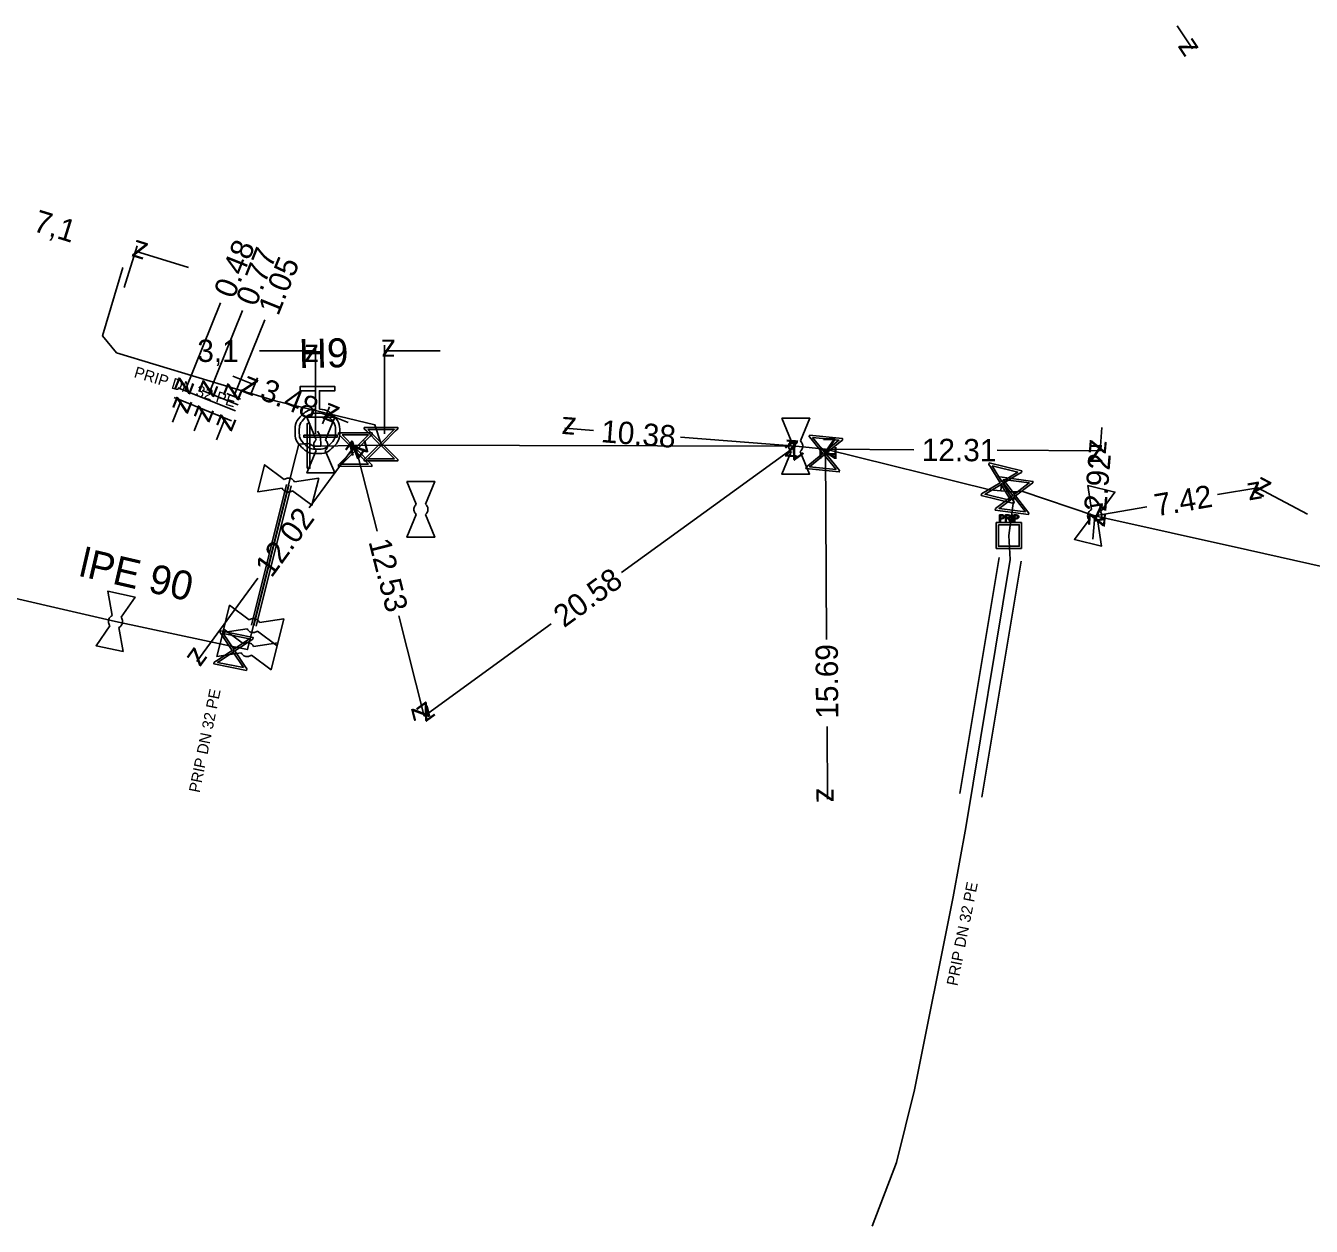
# Model space of a CAD drawing. Extents: x -638315 to -636370, y -1116147 to -1115110.
# Drawn here: x -637168.7 to -637111.1, y -1116084.9 to -1116031.1 of the extents above; entities that cross this region are included whole.
import ezdxf

# ---------------------------------------------------------------- set-up
doc = ezdxf.new("R2010")
doc.units = 0
for name, color, linetype in [('Default', 7, 'Continuous'), ('VP Chránička', 7, 'Continuous'), ('VP Chránička - okraje', 7, 'Continuous'), ('VP Hydrant', 7, 'Continuous'), ('VP Hydrant - popis', 7, 'Continuous'), ('VP Kótování', 7, 'Continuous'), ('VP Lomový bod', 7, 'Continuous'), ('VP Popis přípojky', 7, 'Continuous'), ('VP Přípojka', 7, 'Continuous'), ('VP Řad', 7, 'Continuous'), ('VP Řad - popis', 7, 'Continuous'), ('VP Šachta', 7, 'Continuous'), ('VP Šoupě', 7, 'Continuous')]:
    doc.layers.add(name, color=color, linetype=linetype)

msp = doc.modelspace()

# ---------------------------------------------------------------- linework, layer by layer
at = {"layer": 'Default'}
for points in [[(-637155.578, -1116048.304), (-637155.219, -1116048.333), (-637154.961, -1116048.593), (-637154.67, -1116048.886), (-637154.67, -1116049.302), (-637154.67, -1116049.716), (-637154.963, -1116050.008), (-637155.256, -1116050.3), (-637155.672, -1116050.3), (-637156.084, -1116050.3), (-637156.377, -1116050.008), (-637156.67, -1116049.716), (-637156.67, -1116049.302), (-637156.67, -1116048.886), (-637156.379, -1116048.593), (-637156.121, -1116048.331), (-637155.762, -1116048.304)], [(-637155.672, -1116048.486), (-637156.01, -1116048.486), (-637156.247, -1116048.723), (-637156.484, -1116048.96), (-637156.484, -1116049.298), (-637156.484, -1116049.636), (-637156.247, -1116049.873), (-637156.01, -1116050.111), (-637155.672, -1116050.111), (-637155.336, -1116050.111), (-637155.098, -1116049.873), (-637154.859, -1116049.636), (-637154.859, -1116049.298), (-637154.859, -1116048.96), (-637155.097, -1116048.723), (-637155.334, -1116048.486), (-637155.672, -1116048.486)], [(-637155.724, -1116050.157), (-637155.764, -1116050.123), (-637155.791, -1116050.075), (-637155.833, -1116050.002), (-637155.833, -1116049.92), (-637155.833, -1116049.838), (-637155.79, -1116049.763), (-637155.764, -1116049.716), (-637155.724, -1116049.682)], [(-637155.315, -1116049.682), (-637155.276, -1116049.716), (-637155.249, -1116049.763), (-637155.208, -1116049.838), (-637155.208, -1116049.92), (-637155.208, -1116050.002), (-637155.249, -1116050.075), (-637155.276, -1116050.123), (-637155.316, -1116050.157)], [(-637134.434, -1116050.206), (-637134.475, -1116050.172), (-637134.501, -1116050.124), (-637134.543, -1116050.051), (-637134.543, -1116049.969), (-637134.542, -1116049.887), (-637134.499, -1116049.812), (-637134.474, -1116049.766), (-637134.433, -1116049.731)], [(-637134.024, -1116049.732), (-637133.985, -1116049.767), (-637133.959, -1116049.813), (-637133.917, -1116049.889), (-637133.918, -1116049.971), (-637133.918, -1116050.052), (-637133.959, -1116050.126), (-637133.986, -1116050.173), (-637134.027, -1116050.207)], [(-637157.158, -1116051.458), (-637157.115, -1116051.428), (-637157.062, -1116051.413), (-637156.981, -1116051.39), (-637156.902, -1116051.41), (-637156.822, -1116051.43), (-637156.759, -1116051.489), (-637156.72, -1116051.526), (-637156.697, -1116051.573)], [(-637156.795, -1116051.97), (-637156.838, -1116051.999), (-637156.889, -1116052.014), (-637156.973, -1116052.036), (-637157.052, -1116052.017), (-637157.132, -1116051.997), (-637157.193, -1116051.939), (-637157.232, -1116051.901), (-637157.256, -1116051.854)], [(-637151.237, -1116053.039), (-637151.278, -1116053.005), (-637151.305, -1116052.958), (-637151.346, -1116052.884), (-637151.346, -1116052.803), (-637151.346, -1116052.721), (-637151.303, -1116052.645), (-637151.278, -1116052.599), (-637151.237, -1116052.564)], [(-637150.829, -1116052.564), (-637150.789, -1116052.599), (-637150.763, -1116052.645), (-637150.721, -1116052.721), (-637150.721, -1116052.803), (-637150.721, -1116052.884), (-637150.763, -1116052.958), (-637150.789, -1116053.005), (-637150.83, -1116053.039)], [(-637124.984, -1116053.054), (-637124.955, -1116053.054), (-637124.94, -1116053.057), (-637124.919, -1116053.061), (-637124.905, -1116053.071), (-637124.89, -1116053.08), (-637124.882, -1116053.098), (-637124.873, -1116053.116), (-637124.873, -1116053.137), (-637124.873, -1116053.174), (-637124.896, -1116053.199), (-637124.919, -1116053.224), (-637124.98, -1116053.224)], [(-637124.98, -1116053.191), (-637124.943, -1116053.191), (-637124.928, -1116053.177), (-637124.912, -1116053.163), (-637124.912, -1116053.138), (-637124.912, -1116053.12), (-637124.921, -1116053.108), (-637124.93, -1116053.095), (-637124.945, -1116053.091), (-637124.954, -1116053.088), (-637124.981, -1116053.088)], [(-637124.716, -1116053.181), (-637124.69, -1116053.181), (-637124.675, -1116053.176), (-637124.66, -1116053.17), (-637124.653, -1116053.158), (-637124.646, -1116053.147), (-637124.646, -1116053.132), (-637124.646, -1116053.113), (-637124.66, -1116053.099), (-637124.675, -1116053.086), (-637124.707, -1116053.086)], [(-637124.708, -1116053.054), (-637124.67, -1116053.054), (-637124.65, -1116053.062), (-637124.63, -1116053.07), (-637124.618, -1116053.089), (-637124.607, -1116053.109), (-637124.607, -1116053.132), (-637124.607, -1116053.163), (-637124.626, -1116053.184), (-637124.646, -1116053.204), (-637124.687, -1116053.21), (-637124.672, -1116053.218), (-637124.664, -1116053.225), (-637124.648, -1116053.24), (-637124.633, -1116053.263)], [(-637124.342, -1116053.055), (-637124.314, -1116053.055), (-637124.298, -1116053.058), (-637124.278, -1116053.062), (-637124.263, -1116053.072), (-637124.248, -1116053.081), (-637124.24, -1116053.099), (-637124.232, -1116053.116), (-637124.232, -1116053.138), (-637124.232, -1116053.175), (-637124.255, -1116053.2), (-637124.278, -1116053.225), (-637124.338, -1116053.225)], [(-637124.338, -1116053.192), (-637124.301, -1116053.192), (-637124.286, -1116053.178), (-637124.271, -1116053.164), (-637124.271, -1116053.139), (-637124.271, -1116053.121), (-637124.28, -1116053.109), (-637124.288, -1116053.096), (-637124.303, -1116053.092), (-637124.313, -1116053.089), (-637124.339, -1116053.089)], [(-637121.084, -1116053.271), (-637121.115, -1116053.228), (-637121.13, -1116053.175), (-637121.153, -1116053.094), (-637121.133, -1116053.015), (-637121.113, -1116052.935), (-637121.054, -1116052.872), (-637121.018, -1116052.833), (-637120.97, -1116052.81)], [(-637120.573, -1116052.908), (-637120.544, -1116052.95), (-637120.529, -1116053.002), (-637120.507, -1116053.085), (-637120.526, -1116053.165), (-637120.546, -1116053.244), (-637120.604, -1116053.305), (-637120.641, -1116053.345), (-637120.688, -1116053.368)], [(-637124.668, -1116053.282), (-637124.685, -1116053.255), (-637124.696, -1116053.241), (-637124.706, -1116053.228), (-637124.715, -1116053.222), (-637124.724, -1116053.217), (-637124.733, -1116053.215), (-637124.739, -1116053.213), (-637124.753, -1116053.213)], [(-637164.97, -1116058.02), (-637165.001, -1116057.978), (-637165.018, -1116057.927), (-637165.043, -1116057.844), (-637165.026, -1116057.765), (-637165.008, -1116057.685), (-637164.952, -1116057.622), (-637164.916, -1116057.581), (-637164.87, -1116057.556)], [(-637164.471, -1116057.641), (-637164.439, -1116057.683), (-637164.423, -1116057.735), (-637164.397, -1116057.816), (-637164.414, -1116057.895), (-637164.432, -1116057.975), (-637164.489, -1116058.041), (-637164.524, -1116058.08), (-637164.571, -1116058.105)], [(-637158.723, -1116057.759), (-637158.68, -1116057.729), (-637158.628, -1116057.714), (-637158.547, -1116057.691), (-637158.467, -1116057.711), (-637158.388, -1116057.731), (-637158.325, -1116057.791), (-637158.286, -1116057.827), (-637158.263, -1116057.874)], [(-637158.361, -1116058.271), (-637158.404, -1116058.3), (-637158.455, -1116058.315), (-637158.539, -1116058.337), (-637158.618, -1116058.318), (-637158.697, -1116058.298), (-637158.759, -1116058.24), (-637158.798, -1116058.202), (-637158.822, -1116058.155)], [(-637158.991, -1116058.835), (-637158.948, -1116058.804), (-637158.895, -1116058.79), (-637158.814, -1116058.767), (-637158.735, -1116058.787), (-637158.655, -1116058.806), (-637158.592, -1116058.866), (-637158.553, -1116058.902), (-637158.53, -1116058.95)], [(-637158.628, -1116059.346), (-637158.671, -1116059.376), (-637158.723, -1116059.391), (-637158.806, -1116059.413), (-637158.885, -1116059.393), (-637158.965, -1116059.374), (-637159.026, -1116059.316), (-637159.066, -1116059.278), (-637159.089, -1116059.231)]]:
    msp.add_open_spline(points, degree=3, dxfattribs=at)
at = {"layer": 'VP Chránička'}
for points in [[(-637156.95, -1116051.72), (-637158.52, -1116058.02)], [(-637125.113, -1116054.968), (-637126.873, -1116065.538)], [(-637124.127, -1116055.132), (-637125.887, -1116065.702)]]:
    msp.add_lwpolyline(points, dxfattribs=at)
at = {"layer": 'VP Chránička - okraje'}
for points in [[(-637158.629, -1116057.993), (-637157.059, -1116051.693)], [(-637156.841, -1116051.747), (-637158.411, -1116058.047)]]:
    msp.add_lwpolyline(points, dxfattribs=at)
at = {"layer": 'VP Hydrant'}
msp.add_lwpolyline([(-637155.762, -1116048.304), (-637155.762, -1116047.484), (-637156.451, -1116047.484), (-637156.451, -1116047.3), (-637154.889, -1116047.3), (-637154.889, -1116047.484), (-637155.578, -1116047.484), (-637155.578, -1116048.304)], dxfattribs=at)
at = {"layer": 'VP Kótování'}
for points in [[(-637117.127, -1116031.128), (-637116.44, -1116032.16)], [(-637164.337, -1116042.849), (-637163.756, -1116040.984)], [(-637161.443, -1116041.965), (-637163.83, -1116041.222)], [(-637160.014, -1116043.537), (-637161.596, -1116047.477)], [(-637159.027, -1116043.889), (-637160.519, -1116047.599)], [(-637158.024, -1116044.3), (-637159.412, -1116047.743)], [(-637158.26, -1116045.692), (-637155.76, -1116045.692)], [(-637155.76, -1116049.42), (-637155.76, -1116045.442)], [(-637152.662, -1116049.42), (-637152.662, -1116045.442)], [(-637150.162, -1116045.692), (-637152.662, -1116045.692)], [(-637159.464, -1116046.831), (-637158.49, -1116047.223)], [(-637159.336, -1116048.384), (-637161.92, -1116047.346)], [(-637158.668, -1116047.665), (-637158.359, -1116046.898)], [(-637162.166, -1116048.897), (-637161.775, -1116047.923)], [(-637159.515, -1116048.83), (-637162.099, -1116047.792)], [(-637159.229, -1116048.118), (-637160.844, -1116047.469)], [(-637159.124, -1116047.859), (-637159.737, -1116047.612)], [(-637161.197, -1116049.284), (-637160.805, -1116048.31)], [(-637159.515, -1116048.829), (-637161.13, -1116048.18)], [(-637159.515, -1116048.829), (-637160.128, -1116048.582)], [(-637155.439, -1116048.965), (-637155.13, -1116048.198)], [(-637154.287, -1116048.915), (-637155.261, -1116048.523)], [(-637160.196, -1116049.687), (-637159.803, -1116048.713)], [(-637143.293, -1116049.261), (-637144.58, -1116049.16)], [(-637120.504, -1116049.134), (-637120.59, -1116050.18)], [(-637139.396, -1116049.566), (-637134.23, -1116049.97)], [(-637156.033, -1116052.74), (-637153.974, -1116049.924)], [(-637152.99, -1116053.786), (-637153.974, -1116049.924)], [(-637142.033, -1116055.641), (-637134.23, -1116049.97)], [(-637128.93, -1116050.13), (-637132.9, -1116050.106)], [(-637132.846, -1116058.633), (-637132.9, -1116050.106)], [(-637125.197, -1116050.152), (-637120.59, -1116050.18)], [(-637115.33, -1116052.142), (-637113.52, -1116051.83)], [(-637111.284, -1116053.022), (-637113.52, -1116051.83)], [(-637120.916, -1116054.136), (-637120.83, -1116053.09)], [(-637118.491, -1116052.687), (-637120.83, -1116053.09)], [(-637158.339, -1116055.895), (-637161.07, -1116059.63)], [(-637152.026, -1116057.573), (-637150.88, -1116062.07)], [(-637145.195, -1116057.938), (-637150.88, -1116062.07)], [(-637132.821, -1116062.541), (-637132.8, -1116065.8)]]:
    msp.add_lwpolyline(points, dxfattribs=at)
at = {"layer": 'VP Lomový bod'}
for points in [[(-637156.145, -1116048.67), (-637154.895, -1116048.67), (-637155.315, -1116049.682)], [(-637155.724, -1116049.682), (-637156.145, -1116048.67)], [(-637134.852, -1116048.718), (-637133.602, -1116048.721), (-637134.024, -1116049.732)], [(-637134.433, -1116049.731), (-637134.852, -1116048.718)], [(-637155.316, -1116050.157), (-637154.895, -1116051.17), (-637156.145, -1116051.17), (-637155.724, -1116050.157)], [(-637134.027, -1116050.207), (-637133.608, -1116051.221), (-637134.858, -1116051.218), (-637134.434, -1116050.206)], [(-637157.256, -1116051.854), (-637158.341, -1116052.018), (-637158.039, -1116050.805), (-637157.158, -1116051.458)], [(-637155.613, -1116051.408), (-637155.915, -1116052.621), (-637156.795, -1116051.97)], [(-637156.697, -1116051.573), (-637155.613, -1116051.408)], [(-637151.659, -1116051.553), (-637150.409, -1116051.553), (-637150.829, -1116052.564)], [(-637151.237, -1116052.564), (-637151.659, -1116051.553)], [(-637121.136, -1116051.726), (-637119.923, -1116052.026), (-637120.573, -1116052.908)], [(-637120.97, -1116052.81), (-637121.136, -1116051.726)], [(-637150.83, -1116053.039), (-637150.409, -1116054.053), (-637151.659, -1116054.053), (-637151.237, -1116053.039)], [(-637120.688, -1116053.368), (-637120.523, -1116054.453), (-637121.736, -1116054.153), (-637121.084, -1116053.271)], [(-637164.87, -1116057.556), (-637165.069, -1116056.477), (-637163.847, -1116056.739), (-637164.471, -1116057.641)], [(-637158.822, -1116058.155), (-637159.907, -1116058.319), (-637159.605, -1116057.106), (-637158.723, -1116057.759)], [(-637157.179, -1116057.709), (-637157.48, -1116058.922), (-637158.361, -1116058.271)], [(-637158.263, -1116057.874), (-637157.179, -1116057.709)], [(-637164.371, -1116059.183), (-637165.593, -1116058.921), (-637164.97, -1116058.02)], [(-637164.571, -1116058.105), (-637164.371, -1116059.183)], [(-637159.089, -1116059.231), (-637160.174, -1116059.395), (-637159.872, -1116058.182), (-637158.991, -1116058.835)], [(-637157.446, -1116058.785), (-637157.748, -1116059.998), (-637158.628, -1116059.346)], [(-637158.53, -1116058.95), (-637157.446, -1116058.785)]]:
    msp.add_lwpolyline(points, dxfattribs=at)
at = {"layer": 'VP Přípojka'}
for points in [[(-637152.812, -1116049.929), (-637152.82, -1116049.88), (-637153.09, -1116049.01), (-637157.57, -1116047.94), (-637164.67, -1116045.79), (-637165.3, -1116045.02), (-637164.4, -1116041.96)], [(-637155.516, -1116049.967), (-637155.53, -1116049.517), (-637155.67, -1116049.3)], [(-637153.974, -1116050.124), (-637153.974, -1116049.945)], [(-637132.95, -1116050.3), (-637132.9, -1116050.106)], [(-637130.81, -1116084.95), (-637129.71, -1116082.09), (-637128.9, -1116078.83), (-637127.18, -1116070.18), (-637126.61, -1116067.07), (-637124.62, -1116055.05), (-637124.68, -1116053.97), (-637124.44, -1116052.19), (-637124.42, -1116052.02)], [(-637125.037, -1116051.971), (-637125.01, -1116051.63)], [(-637159.4, -1116058.97), (-637159.434, -1116059.139), (-637159.469, -1116059.308)]]:
    msp.add_lwpolyline(points, dxfattribs=at)
at = {"layer": 'VP Řad'}
for points in [[(-637155.75, -1116049.97), (-637155.516, -1116049.967), (-637153.974, -1116049.945), (-637152.812, -1116049.929), (-637134.23, -1116049.97), (-637132.9, -1116050.106), (-637125.536, -1116051.933), (-637125.037, -1116051.971), (-637124.42, -1116052.02), (-637124.09, -1116051.99), (-637120.83, -1116053.09), (-637113.988, -1116054.623), (-637104.14, -1116056.83), (-637097.77, -1116058.25), (-637096.525, -1116058.569), (-637096.41, -1116058.59), (-637095.95, -1116058.7), (-637095.421, -1116054.952), (-637095.37, -1116054.59), (-637095.16, -1116053.01), (-637092.38, -1116035.31), (-637092.034, -1116033.336), (-637091.08, -1116027.9)], [(-637155.75, -1116049.97), (-637155.805, -1116049.965), (-637155.86, -1116049.96), (-637156.06, -1116049.854), (-637156.51, -1116049.88), (-637156.75, -1116050.8), (-637157.78, -1116054.945), (-637158.81, -1116059.09), (-637159.4, -1116058.97), (-637162.06, -1116058.4), (-637164.72, -1116057.83), (-637167.635, -1116057.155), (-637170.55, -1116056.48)]]:
    msp.add_lwpolyline(points, dxfattribs=at)
at = {"layer": 'VP Šachta'}
for points in [[(-637125.091, -1116053.341), (-637125.091, -1116053.054), (-637124.984, -1116053.054)], [(-637124.981, -1116053.088), (-637125.054, -1116053.088), (-637125.054, -1116053.191)], [(-637125.054, -1116053.191), (-637124.98, -1116053.191)], [(-637124.835, -1116053.341), (-637124.835, -1116053.054), (-637124.708, -1116053.054)], [(-637124.707, -1116053.086), (-637124.797, -1116053.086), (-637124.797, -1116053.181)], [(-637124.797, -1116053.181), (-637124.716, -1116053.181)], [(-637124.544, -1116053.342), (-637124.544, -1116053.055), (-637124.507, -1116053.055), (-637124.507, -1116053.342), (-637124.544, -1116053.342)], [(-637124.45, -1116053.342), (-637124.45, -1116053.055), (-637124.342, -1116053.055)], [(-637124.339, -1116053.089), (-637124.412, -1116053.089), (-637124.412, -1116053.192)], [(-637124.412, -1116053.192), (-637124.338, -1116053.192)], [(-637124.115, -1116053.392), (-637124.115, -1116054.553), (-637125.245, -1116054.553), (-637125.245, -1116053.392), (-637124.115, -1116053.392)], [(-637125.149, -1116053.491), (-637125.149, -1116054.454), (-637124.211, -1116054.454), (-637124.211, -1116053.491), (-637125.149, -1116053.491)], [(-637124.98, -1116053.224), (-637125.054, -1116053.224), (-637125.054, -1116053.341), (-637125.091, -1116053.341)], [(-637124.753, -1116053.213), (-637124.797, -1116053.213), (-637124.797, -1116053.341), (-637124.835, -1116053.341)], [(-637124.633, -1116053.263), (-637124.583, -1116053.341), (-637124.631, -1116053.341), (-637124.668, -1116053.282)], [(-637124.338, -1116053.225), (-637124.412, -1116053.225), (-637124.412, -1116053.342), (-637124.45, -1116053.342)]]:
    msp.add_lwpolyline(points, dxfattribs=at)
at = {"layer": 'VP Šoupě'}
for points in [[(-637156.133, -1116050.96), (-637156.133, -1116048.96), (-637156.008, -1116048.96), (-637156.008, -1116050.96), (-637156.133, -1116050.96)], [(-637153.57, -1116049.13), (-637152.07, -1116049.13), (-637152.07, -1116049.196), (-637152.164, -1116049.284), (-637152.757, -1116049.879), (-637152.07, -1116050.564), (-637152.07, -1116050.63), (-637153.57, -1116050.63), (-637153.57, -1116050.564), (-637152.882, -1116049.879), (-637153.476, -1116049.285), (-637153.57, -1116049.196), (-637153.57, -1116049.13)], [(-637156.28, -1116049.47), (-637154.78, -1116049.47), (-637154.78, -1116049.564), (-637156.28, -1116049.564), (-637156.28, -1116049.47)], [(-637154.722, -1116049.371), (-637153.222, -1116049.375), (-637153.223, -1116049.441), (-637153.317, -1116049.529), (-637153.911, -1116050.122), (-637153.226, -1116050.809), (-637153.226, -1116050.875), (-637154.726, -1116050.871), (-637154.726, -1116050.806), (-637154.036, -1116050.122), (-637154.629, -1116049.527), (-637154.723, -1116049.437), (-637154.722, -1116049.371)], [(-637154.565, -1116049.466), (-637153.973, -1116050.06), (-637153.381, -1116049.468), (-637154.565, -1116049.466)], [(-637153.413, -1116049.224), (-637152.819, -1116049.816), (-637152.228, -1116049.224), (-637153.413, -1116049.224)], [(-637133.62, -1116049.477), (-637132.127, -1116049.63), (-637132.134, -1116049.695), (-637132.236, -1116049.773), (-637132.887, -1116050.305), (-637132.273, -1116051.056), (-637132.28, -1116051.122), (-637133.772, -1116050.969), (-637133.766, -1116050.904), (-637133.011, -1116050.292), (-637133.542, -1116049.641), (-637133.626, -1116049.543), (-637133.62, -1116049.477)], [(-637133.473, -1116049.586), (-637132.943, -1116050.236), (-637132.294, -1116049.707), (-637133.473, -1116049.586)], [(-637153.378, -1116050.781), (-637153.974, -1116050.184), (-637154.569, -1116050.778), (-637153.378, -1116050.781)], [(-637152.222, -1116050.536), (-637152.819, -1116049.941), (-637153.413, -1116050.536), (-637152.222, -1116050.536)], [(-637132.422, -1116051.013), (-637132.955, -1116050.36), (-637133.607, -1116050.892), (-637132.422, -1116051.013)], [(-637125.557, -1116050.721), (-637124.101, -1116051.081), (-637124.117, -1116051.145), (-637124.229, -1116051.208), (-637124.948, -1116051.643), (-637124.445, -1116052.473), (-637124.461, -1116052.537), (-637125.917, -1116052.177), (-637125.901, -1116052.113), (-637125.068, -1116051.613), (-637125.503, -1116050.894), (-637125.573, -1116050.785), (-637125.557, -1116050.721)], [(-637125.427, -1116050.85), (-637124.993, -1116051.567), (-637124.277, -1116051.134), (-637125.427, -1116050.85)], [(-637125.083, -1116051.346), (-637123.597, -1116051.546), (-637123.605, -1116051.612), (-637123.71, -1116051.686), (-637124.377, -1116052.196), (-637123.788, -1116052.968), (-637123.797, -1116053.033), (-637125.284, -1116052.833), (-637125.275, -1116052.767), (-637124.501, -1116052.18), (-637125.011, -1116051.512), (-637125.092, -1116051.411), (-637125.083, -1116051.346)], [(-637124.94, -1116051.46), (-637124.431, -1116052.126), (-637123.766, -1116051.618), (-637124.94, -1116051.46)], [(-637124.586, -1116052.409), (-637125.023, -1116051.688), (-637125.743, -1116052.124), (-637124.586, -1116052.409)], [(-637123.935, -1116052.92), (-637124.447, -1116052.25), (-637125.116, -1116052.761), (-637123.935, -1116052.92)], [(-637158.85, -1116060.024), (-637160.319, -1116059.724), (-637160.306, -1116059.659), (-637160.197, -1116059.592), (-637159.497, -1116059.128), (-637160.033, -1116058.319), (-637160.019, -1116058.254), (-637158.55, -1116058.554), (-637158.563, -1116058.619), (-637159.375, -1116059.153), (-637158.91, -1116059.853), (-637158.836, -1116059.959), (-637158.85, -1116060.024)], [(-637159.889, -1116058.376), (-637159.423, -1116059.079), (-637158.722, -1116058.615), (-637159.889, -1116058.376)], [(-637158.985, -1116059.901), (-637159.448, -1116059.201), (-637160.146, -1116059.664), (-637158.985, -1116059.901)]]:
    msp.add_lwpolyline(points, dxfattribs=at)

# ---------------------------------------------------------------- texts
at = {"layer": 'VP Hydrant - popis'}
msp.add_text('H9', height=1.3, rotation=1, dxfattribs=at).set_placement((-637156.492, -1116046.465))
at = {"layer": 'VP Kótování'}
for s, rotation, p in [('z', 303.65957, (-637117.133, -1116032.021)), ('7,1', 342.71423, (-637168.464, -1116040.304)), ('z', 162.71423, (-637163.204, -1116040.893)), ('0.48', 68.13219, (-637159.42, -1116043.398)), ('0.77', 68.0875, (-637158.432, -1116043.75)), ('1.05', 68.04601, (-637157.43, -1116044.162)), ('z', 180, (-637152.162, -1116045.192)), ('z', 338.07021, (-637159.141, -1116047.5)), ('z', 248.13217, (-637161.873, -1116046.826)), ('z', 248.08753, (-637160.797, -1116046.949)), ('z', 248.04599, (-637159.689, -1116047.092)), ('3.48', 338.07019, (-637158.311, -1116047.834)), ('z', 68.13219, (-637161.497, -1116048.573)), ('z', 158.07023, (-637154.611, -1116048.246)), ('z', 68.0875, (-637160.528, -1116048.961)), ('z', 68.04601, (-637159.526, -1116049.364)), ('z', 175.5251, (-637144.043, -1116048.701)), ('10.38', 355.52512, (-637142.983, -1116049.787)), ('z', 53.82967, (-637153.865, -1116050.623)), ('z', 104.29127, (-637153.366, -1116050.285)), ('z', 36.0069, (-637134.341, -1116050.668)), ('z', 355.52509, (-637134.767, -1116050.429)), ('z', 179.65556, (-637132.397, -1116049.609)), ('12.31', 359.65558, (-637128.583, -1116050.632)), ('z', 265.28526, (-637121.047, -1116049.641)), ('z', 90.36507, (-637132.397, -1116050.603)), ('z', 359.6556, (-637121.093, -1116050.677)), ('2.92', 85.28523, (-637120.315, -1116052.928)), ('z', 151.94021, (-637112.844, -1116051.624)), ('7.42', 9.77976, (-637118.062, -1116053.12)), ('z', 9.77976, (-637113.928, -1116052.408)), ('z', 189.7798, (-637120.422, -1116052.512)), ('12.02', 53.82967, (-637157.729, -1116055.907)), ('z', 85.28523, (-637120.373, -1116053.629)), ('12.53', 284.29123, (-637153.388, -1116054.248)), ('20.58', 36.0069, (-637144.618, -1116058.137)), ('15.69', 90.36507, (-637132.323, -1116062.188)), ('z', 233.82965, (-637161.179, -1116058.931)), ('z', 284.29125, (-637151.488, -1116061.709)), ('z', 216.00688, (-637150.769, -1116061.372)), ('z', 270.36505, (-637133.303, -1116065.303))]:
    msp.add_text(s, height=1, rotation=rotation, dxfattribs=at).set_placement(p)
for s, p in [('3,1', (-637161.055, -1116046.192)), ('z', (-637156.26, -1116046.192))]:
    msp.add_text(s, height=1, dxfattribs=at).set_placement(p)
at = {"layer": 'VP Popis přípojky'}
for rotation, p in [(343.1528, (-637163.926, -1116046.866)), (78.46206, (-637160.949, -1116065.535)), (78.75379, (-637126.985, -1116074.197))]:
    msp.add_text('PRIP DN 32 PE', height=0.5, rotation=rotation, dxfattribs=at).set_placement(p)
at = {"layer": 'VP Řad - popis'}
msp.add_text('lPE 90', height=1.3, rotation=346.96233, dxfattribs=at).set_placement((-637166.417, -1116055.777))

doc.saveas('drawing.dxf')
